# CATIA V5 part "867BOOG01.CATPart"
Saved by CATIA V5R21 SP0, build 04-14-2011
Part number: 867BOOG01
Source: Unknown
Bounding box of the stored display mesh (mm): x -19 to 21, y -27 to 27, z -17.5 to 62
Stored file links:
  C:\Users\ALI OZGUN\Desktop\alhan\867BOOG01.CATPart
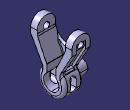
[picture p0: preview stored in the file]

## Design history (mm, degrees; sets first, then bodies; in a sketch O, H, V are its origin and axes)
Body1 "pimli" (main body)
  Solid1: solid without history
